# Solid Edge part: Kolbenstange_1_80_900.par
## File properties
Username: ahadarics
Dokumentum tartalom típus: 0
Author: ahadarics
Last saved by: ahadarics
Revision: 92
Sűrűség: 0,000 kg/m^3
Pontosság: 0,990
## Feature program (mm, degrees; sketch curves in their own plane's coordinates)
base feature "unnamed BaseFeature 1"
thread "unnamed Thread 1"
chamfer "Letörés_1"  SetBackValue2 = 20 deg
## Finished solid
Body 1: solid body, 19 faces, 27 edges, 11 vertices.
  Faces by surface: plane 8, cylinder 5, cone 3, torus 3
  Edges by curve: circle 15, line 7, curve on surface 3, ellipse 2
Bounding box of the edges (mm; curved faces can reach further): 80.000 x 80.000 x 1074.000, from (-40, -40, -79.5) to (40, 40, 994.5).
Cylindrical faces by radius (mm): R8.75 x1, R10 x1, R12.25 x1, R12.5 x1, R40 x1
Conical faces (half-angle, radius in mm at the cone's reference point): 20 deg R10 x1, 30 deg R12.375 x1, 60 deg R9.375 x1
Toroidal faces (ring radius, tube radius in mm): R9.15 r0.4 x2, R10.45 r1.8 x1
Planar faces by outward normal: +x 1, +z 3, -x 1, -z 1, oblique 2
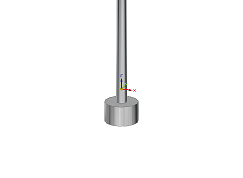
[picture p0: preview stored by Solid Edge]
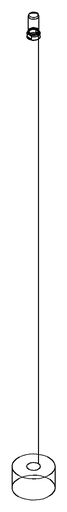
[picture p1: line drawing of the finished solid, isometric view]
